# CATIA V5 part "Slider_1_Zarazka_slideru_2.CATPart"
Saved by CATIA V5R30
Part number: Slider_1_Zarazka_slideru_2
Publications: "DrillHole_CapScrew_E1200_2.3_", "DrillHole_CapScrew_E1200_2.4_"
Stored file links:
  E:\Bakalarka\Model\Forma_v7\Slider_1_Zarazka_slideru_2.CATPart
  E:\Bakalarka\Model\Forma_v7\Slider_1.CATProduct
  E:\Bakalarka\Model\Forma_v7\TlgItf_Zarazka_slideru.CATProduct

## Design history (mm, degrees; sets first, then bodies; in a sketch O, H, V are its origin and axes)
Body1 (main body)
Body2 "DrillHole"
  Solid1: linked copy from another document
Body3 "DrillHole"
  Solid2: linked copy from another document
